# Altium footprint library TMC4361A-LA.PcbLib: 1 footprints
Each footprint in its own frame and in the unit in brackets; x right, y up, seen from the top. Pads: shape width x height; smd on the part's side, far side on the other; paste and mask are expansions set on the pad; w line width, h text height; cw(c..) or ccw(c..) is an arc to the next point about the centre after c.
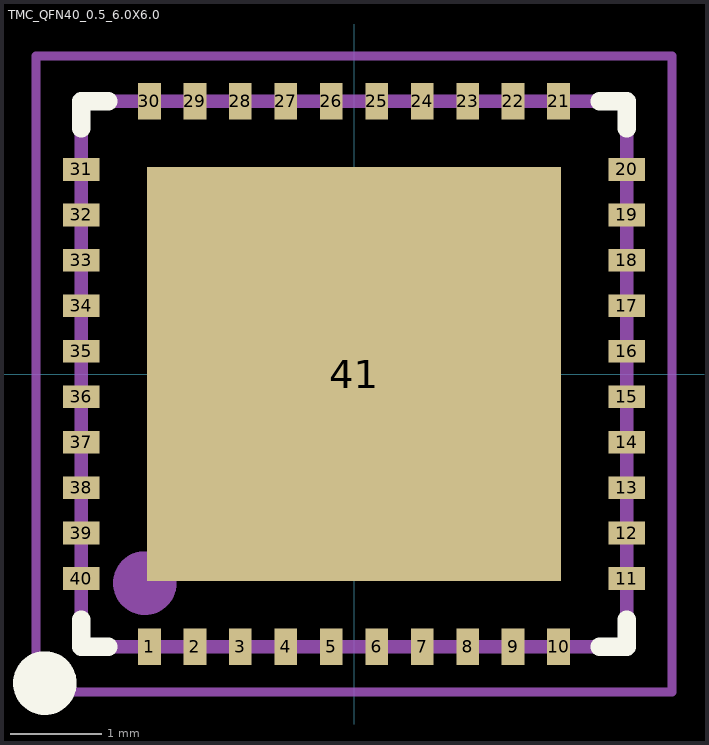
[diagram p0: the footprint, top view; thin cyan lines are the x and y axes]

## TMC_QFN40_0.5_6.0X6.0 [mm]
pads (41):
  rect 0.25x0.4 smd: 1(-2.25,-3) 2(-1.75,-3) 3(-1.25,-3) 4(-0.75,-3) 5(-0.25,-3) 6(0.25,-3) 7(0.75,-3) 8(1.25,-3) 9(1.75,-3) 10(2.25,-3) 21(2.25,3) 22(1.75,3) 23(1.25,3) 24(0.75,3) 25(0.25,3) 26(-0.25,3) 27(-0.75,3) 28(-1.25,3) 29(-1.75,3) 30(-2.25,3)
  rect 0.4x0.25 smd: 11(3,-2.25) 12(3,-1.75) 13(3,-1.25) 14(3,-0.75) 15(3,-0.25) 16(3,0.25) 17(3,0.75) 18(3,1.25) 19(3,1.75) 20(3,2.25) 31(-3,2.25) 32(-3,1.75) 33(-3,1.25) 34(-3,0.75) 35(-3,0.25) 36(-3,-0.25) 37(-3,-0.75) 38(-3,-1.25) 39(-3,-1.75) 40(-3,-2.25)
  rect 4.55x4.55 smd paste-25.4: 41(0,0)
L26-Silk Screen Top (Multiple PADS layers...):
  circle w0.5: c-3.4,-3.4 r0.1
  lines w0.2: -3,-2.7 -3,-3 -2.7,-3 ; -3,2.7 -3,3 -2.7,3 ; 2.7,-3 3,-3 3,-2.7 ; 2.7,3 3,3 3,2.7
L23-Paste Mask Top (Multiple PADS layers...):
  region: -2.025,2.025 -0.875,2.025 -0.875,0.875 -2.025,0.875
  region: -2.025,0.575 -0.875,0.575 -0.875,-0.575 -2.025,-0.575
  region: -2.025,-0.875 -0.875,-0.875 -0.875,-2.025 -2.025,-2.025
  region: 0.875,-0.875 2.025,-0.875 2.025,-2.025 0.875,-2.025
  region: -0.575,-0.875 0.575,-0.875 0.575,-2.025 -0.575,-2.025
  region: -0.575,0.575 0.575,0.575 0.575,-0.575 -0.575,-0.575
  region: -0.575,2.025 0.575,2.025 0.575,0.875 -0.575,0.875
  region: 0.875,2.025 2.025,2.025 2.025,0.875 0.875,0.875
  region: 0.875,0.575 2.025,0.575 2.025,-0.575 0.875,-0.575
L13:
  circle w0.5: c-2.3,-2.3 r0.1
  lines w0.15: -3,-3 -3,3 3,3 3,-3 -3,-3
L15 (Multiple PADS layers...):
  lines w0.1: -3.5,-3.5 -3.5,3.5 3.5,3.5 3.5,-3.5 -3.5,-3.5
